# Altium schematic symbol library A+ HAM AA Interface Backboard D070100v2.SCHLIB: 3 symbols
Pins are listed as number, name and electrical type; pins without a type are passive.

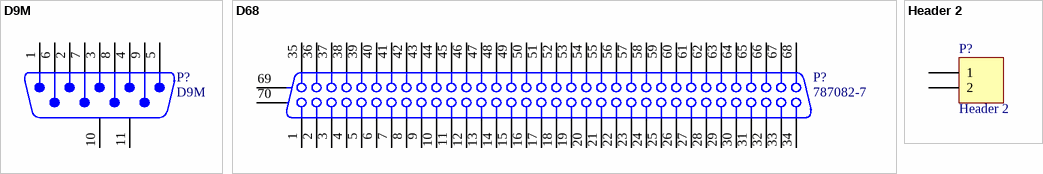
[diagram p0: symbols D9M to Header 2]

## D9M
designator P?
9 Position D-Sub Plug, Male Pins Connector; Manufacturer: TE Connectivity; Manufacturer Part Number: 5747871-8; Description: CONN D-SUB PLUG 9POS VERT SOLDER; Plating: Tin; Body Material: Steel; Voltage Rating: 125V; Current Rating: 6A; Max Voltage Rating (DC): 250.25kV; Number of Positions: 9; Number of Ports: 1; Max Supply Voltage (AC): 250V; Mating Connector Lock: Yes (With); PCB Mount Retention: With; PCB Mounting Orientation: Vertical; Preloaded: Yes; Sealable: No (Without); Pitch: 0.108inch; PCB Thickness: 2.36mm; Contact Post Length: 0.125inch; Hole Diameter: 0.12inch; Approvals: UL
signal-integrity model D Subminiature
footprint DB9/M
pins: 1, 2, 3, 4, 5, 6, 7, 8, 9, 10 MH1, 11 MH2

## D68
designator P?, comment 787082-7
68 Position D-Type Receptacle, Female Sockets Connector; Manufacturer: TE Connectivity; Manufacturer Part Number: 7870827; Description: CONN D-TYPE RCPT 68POS R/A SLDR; Plating: Bright,Copper; Voltage Rating: 30V; Current Rating: 1A; Number of Positions: 68; Connector Type: Receptacle,Connector; Number of Ports: 1; Shielding: Shielded; Mating Alignment: No (Without); Mating Connector Lock: Yes (With); PCB Mount Retention: With; PCB Mounting Orientation: Right Angle; Pitch: 0.05inch; PCB Thickness: 1.57mm; Contact Post Length: 0.1inch; Hole Diameter: 0.109inch; Approvals: UL
footprint 787082-7 (Connector; D Subminiature 050 Series; 68 Position; Right Angle)
signal-integrity model D Subminiature
pins: 1, 2, 3, 4, 5, 6, 7, 8, 9, 10, 11, 12, 13, 14, 15, 16, 17, 18, 19, 20, 21, 22, 23, 24, 25, 26, 27, 28, 29, 30, 31, 32, 33, 34, 35, 36, 37, 38, 39, 40, 41, 42, 43, 44, 45, 46, 47, 48, 49, 50, 51, 52, 53, 54, 55, 56, 57, 58, 59, 60, 61, 62, 63, 64, 65, 66, 67, 68, 69 MH1, 70 MH2

## Header 2
designator P?
Connector Header Through Hole 2 position 0.100" (2.54mm); Manufacturer: Molex; Description: Connector Wire to Board Header 2 Position 2.54mm Solder Stra; Contact Resistance: 10mR; Max Current Rating: 4A; Voltage Rating: 250V; Number of Positions: 2; Gender: Male; Insulation Resistance: 500GR; Approvals: UL,CSA; Glow Wire Compliant: Non-compliant
footprint HDR1X2 (Connector; Header; 2 Position)
signal-integrity model Connector
pins: 1, 2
